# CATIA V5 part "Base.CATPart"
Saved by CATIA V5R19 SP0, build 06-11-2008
Part number: Base
Publications: "Demi_longueur"
Bounding box of the stored display mesh (mm): x -40 to 40, y -40 to 40, z 0 to 0
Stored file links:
  F:\IAO\Catia\Base.CATPart
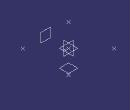
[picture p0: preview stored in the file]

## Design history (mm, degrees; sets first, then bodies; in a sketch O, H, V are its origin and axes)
Parameters
  Demi_longueur = 40 mm
Set1 "Set1"
  Point1: (40 {= Demi_longueur}, 40 {= Demi_longueur}, 0)
  Point2: (40 {= Demi_longueur}, -40 {= -Demi_longueur}, 0)
  Point3: (-40 {= -Demi_longueur}, 40 {= Demi_longueur}, 0)
  Point4: (-40 {= -Demi_longueur}, -40 {= -Demi_longueur}, 0)
  Plane1: type Offset, Offset -30, RefPlane xy-plane
  Point5: (0, 0, 0)
  Point6: (6, 0, 0)
  Plane2: type Offset, Offset -40 {= -Demi_longueur}, RefPlane zx-plane
Body1 (main body)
